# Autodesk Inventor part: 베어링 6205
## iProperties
Created: 2015-10
Part Number: 베어링 6205
Material: 강, 연강
Description: 깊은 그루브 볼 베어링
Document SubType Name: Modeling
Standard: KS B 2023
Designer: mdu
Standards Organization: KS
Language: ko-KR
Size Designation: 6205 - 25 x 52 x 15
Categories: <MemberInstance><Categories><Category DisplayName="샤프트 부품" InternalName="7f7aeb1f-a693-4053-b835-cee3144e0d98" Mnemonic="SHFT"><Category DisplayName="베어링" Inter
Density: 1 g/cm^3
IsCustomPart: 1
Author: mdu
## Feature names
1. IDS_ARRAYBALL[SIMPL:T] [Circular Pattern]
